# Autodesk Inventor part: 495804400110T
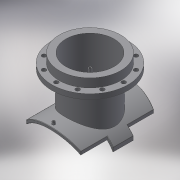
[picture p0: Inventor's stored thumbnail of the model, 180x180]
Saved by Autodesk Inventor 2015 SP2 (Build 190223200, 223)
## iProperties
Created: 2017-10
Part Number: 495804400110T
Material: Generic
Description: PLASSON FLANGED BRANCH SADDLE 250-400X100
Document SubType Name: Modeling
Designer: KIM
Density: 1 g/cm^3
Appearance: Default
Author: KIM
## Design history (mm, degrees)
derived "495904.ipt"
feature "Solid1::495904.ipt"
feature "Solid2::495904.ipt"
tag "TaggingFeature1"
body "Solid1"
other parameters: "d1" = 15, "d2" = 278.1, "d4" = 0, "d5" = 309, "d6" = 75, "d7" = 0, "d11" = 2, "d12" = 225.6, "d13" = 14, "d14" = 135, "d16" = 5 deg, "d18" = 4, "d19" = 14, "d20" = 0, "d21" = 3, "d22" = 0, "d23" = 325, "d36" = 135, "d38" = 0, "d39" = 2, "d42" = 158, "d44" = 88, "d46" = 126.4, "d47" = 16, "d48" = 10.4, "d49" = 77, "d51" = 408, "d53" = 0, "d54" = 18, "d57" = 0, "d59" = 360 deg, "d61" = 22, "d63" = 0, "d_1" = 158, "B_" = 309, "x_" = 15, "D_" = 16, "t_" = 22, "s_" = 18
